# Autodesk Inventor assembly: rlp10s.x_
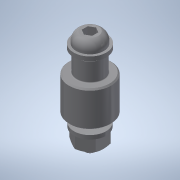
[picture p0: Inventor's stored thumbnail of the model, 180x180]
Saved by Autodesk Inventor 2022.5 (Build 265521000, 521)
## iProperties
Part Number: rlp10s.x_
Material: 一般
Document SubType Name: Assembly
Designer: ImaoCorp
Sending System: SOLIDWORKS 2017-2017317
MC: AMD64
MC_MODEL: Intel64 Family 6 Model 60 Stepping 3, GenuineIntel
OS: Windows_NT
FRU: Parasolid Version 29.0, build 201,  4-17-2017
FORMAT: text
GUISE: transmit
KEY: rlp10s
FILE: rlp10s.x_t
DATE: Wed Sep 04 15:58:18 2019
Author: ImaoCorp
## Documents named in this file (3)
- X:\14_SW2022-Inv2022\00_全2023-1023新製品(TCC)まで\r\rlp10s\RLP10S.iam
- X:\14_SW2022-Inv2022\00_全2023-1023新製品(TCC)まで\r\rlp10s\rlp10s_01.ipt
- X:\14_SW2022-Inv2022\00_全2023-1023新製品(TCC)まで\r\rlp10s\rlp10s_02.ipt
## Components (2 placed, 2 different names)
1. rlp10s_01
2. rlp10s_02
